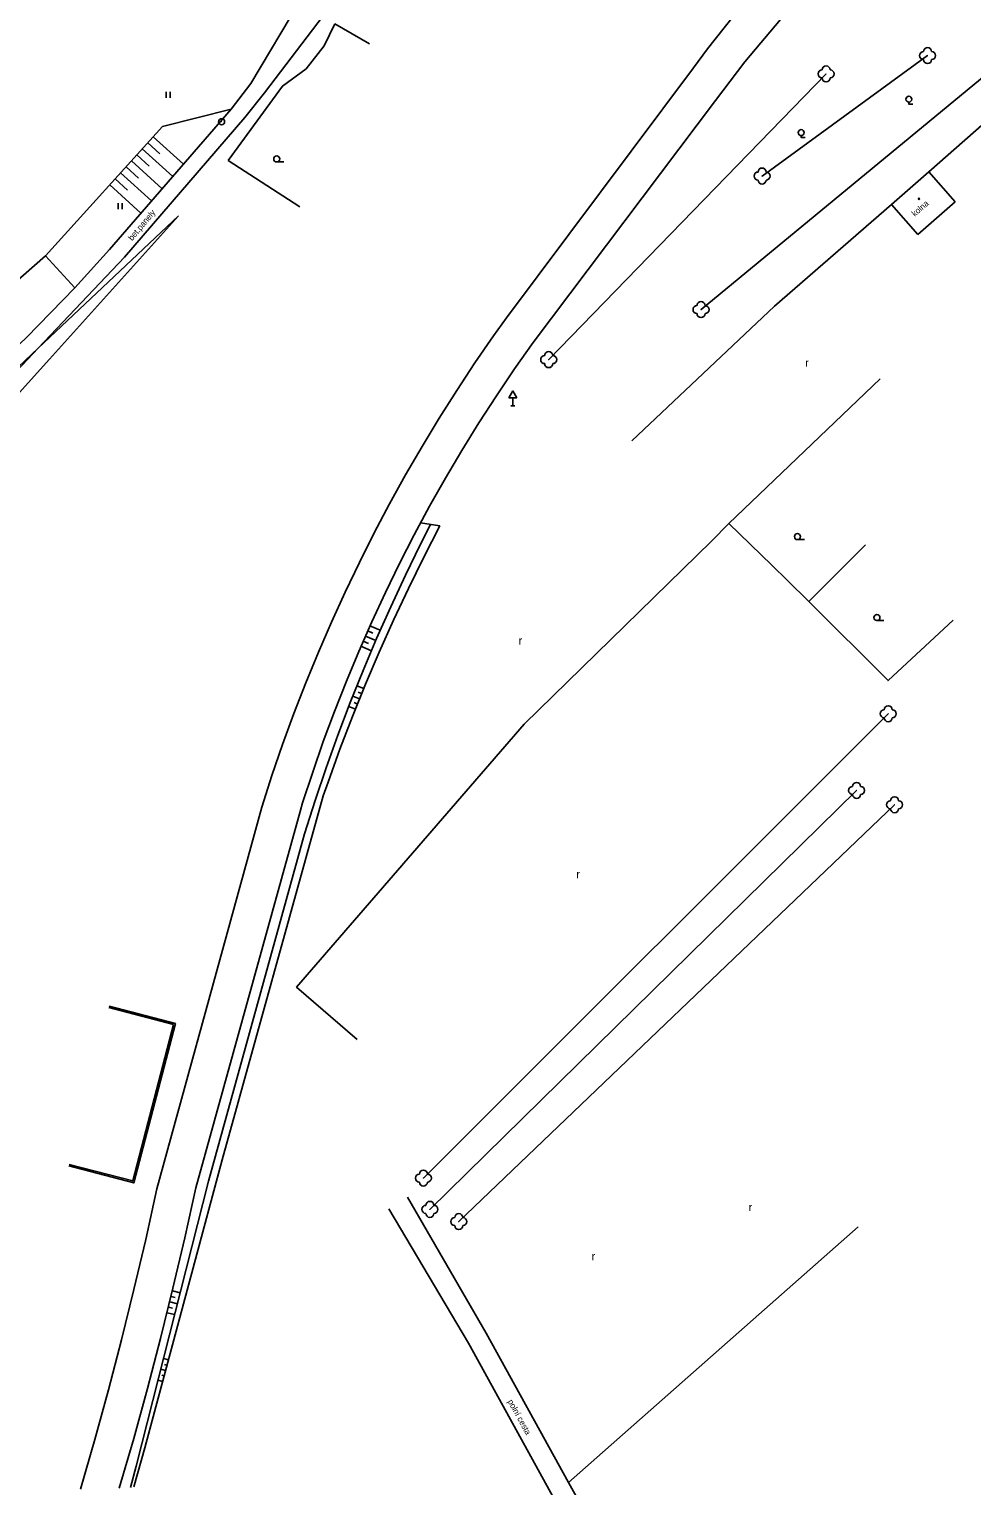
# Model space of a CAD drawing. Extents: x -544674 to -541478, y -1199076 to -1195527.
# Drawn here: x -543908.9 to -543791.2, y -1197598.9 to -1197417 of the extents above; entities that cross this region are included whole.
import ezdxf

# ---------------------------------------------------------------- set-up
doc = ezdxf.new("R2010")
doc.units = 0
for name, color, linetype in [('BUDOVY_MĚŘ', 7, 'Continuous'), ('BUDOVY_NEMĚŘ', 7, 'Continuous'), ('MAP_ZN_BP', 7, 'Continuous'), ('POMOC_POPIS', 7, 'Continuous'), ('ROZHRANÍ_PLOCH', 7, 'Continuous'), ('VÝŠKOPIS', 7, 'Continuous'), ('ZELEŇ', 7, 'Continuous'), ('ZN_BUDOV', 7, 'Continuous'), ('ZN_DOPLŇKOVÉ', 7, 'Continuous'), ('ZN_KULTUR', 7, 'Continuous')]:
    doc.layers.add(name, color=color, linetype=linetype)

msp = doc.modelspace()

# ---------------------------------------------------------------- linework, layer by layer
at = {"layer": 'BUDOVY_MĚŘ'}
for points in [[(-543870.77, -1197416.3), (-543866.43, -1197418.78)], [(-543801.25, -1197438.87), (-543796.59, -1197434.77)]]:
    msp.add_lwpolyline(points, dxfattribs=at)
at = {"layer": 'BUDOVY_NEMĚŘ'}
for points in [[(-543793.29, -1197438.52), (-543796.59, -1197434.77)], [(-543797.95, -1197442.62), (-543801.25, -1197438.87)], [(-543793.29, -1197438.52), (-543797.95, -1197442.62)]]:
    msp.add_lwpolyline(points, dxfattribs=at)
at = {"layer": 'MAP_ZN_BP'}
for radius in [0.375, 0.0005]:
    msp.add_circle((-543884.89, -1197428.531), radius, dxfattribs=at)
at = {"layer": 'ROZHRANÍ_PLOCH'}
for points in [[(-543807.01, -1197397.49), (-543812.18, -1197404.22), (-543824.2, -1197419.43), (-543825.96, -1197421.78)], [(-543799.94, -1197397.74), (-543819.57, -1197421.04), (-543823.21, -1197425.87)], [(-543872.33, -1197408.41), (-543875.02, -1197413.36), (-543881.23, -1197423.75), (-543883.69, -1197426.94)], [(-543869.19, -1197409.61), (-543872.22, -1197415.31), (-543879.55, -1197424.91), (-543882.01, -1197427.98)], [(-543825.96, -1197421.78), (-543849.33, -1197453.01), (-543850.94, -1197455.26), (-543853.27, -1197458.66), (-543855.53, -1197462.09), (-543857.73, -1197465.57), (-543859.86, -1197469.1), (-543861.93, -1197472.66), (-543863.92, -1197476.26), (-543865.84, -1197479.9), (-543867.69, -1197483.58), (-543869.47, -1197487.29), (-543871.18, -1197491.03), (-543872.81, -1197494.81), (-543874.37, -1197498.62), (-543875.86, -1197502.46), (-543877.27, -1197506.33), (-543878.6, -1197510.22), (-543879.86, -1197514.14), (-543892.97, -1197561.85), (-543894.36, -1197568.15), (-543895.83, -1197574.43), (-543897.38, -1197580.7), (-543899.01, -1197586.94), (-543900.71, -1197593.16), (-543902.49, -1197599.36)], [(-543823.21, -1197425.87), (-543846, -1197456.1), (-543848.32, -1197459.4), (-543850.57, -1197462.75), (-543852.76, -1197466.14), (-543854.88, -1197469.58), (-543856.93, -1197473.06), (-543858.92, -1197476.57), (-543860.83, -1197480.13), (-543862.67, -1197483.72), (-543864.44, -1197487.35), (-543866.14, -1197491.01), (-543867.76, -1197494.7), (-543869.31, -1197498.43), (-543870.79, -1197502.19), (-543872.19, -1197505.97), (-543873.52, -1197509.78), (-543874.77, -1197513.62), (-543875.1, -1197514.68), (-543888.1, -1197561.72), (-543889.48, -1197567.95), (-543890.96, -1197574.25), (-543892.52, -1197580.52), (-543894.15, -1197586.78), (-543895.87, -1197593.02), (-543897.66, -1197599.23)], [(-543925.38, -1197473.51), (-543907.78, -1197456.8), (-543897.03, -1197445.43), (-543882.01, -1197427.98)], [(-543883.69, -1197426.94), (-543898.88, -1197444.48), (-543903.21, -1197449.26), (-543909.24, -1197455.47), (-543925.14, -1197470.5)], [(-543861.68, -1197562.88), (-543851.84, -1197579.85), (-543841.58, -1197598.53), (-543835.5, -1197609.42), (-543829.31, -1197618.12), (-543823.7, -1197624.21), (-543819.24, -1197626.66), (-543813.49, -1197627.62), (-543807.65, -1197626.61)], [(-543863.99, -1197564.35), (-543854.05, -1197581.13), (-543837.84, -1197610.66), (-543831.7, -1197619.95), (-543825.41, -1197626.26), (-543819.82, -1197629.04), (-543813.7, -1197630.75), (-543809.54, -1197636.63)]]:
    msp.add_lwpolyline(points, dxfattribs=at)
at = {"layer": 'VÝŠKOPIS'}
for points in [[(-543883.69, -1197426.94), (-543892.25, -1197429.12), (-543906.87, -1197445.29), (-543933.32, -1197468.49)], [(-543890.98, -1197435.36), (-543894.79, -1197431.92)], [(-543892.59, -1197432.54), (-543894.11, -1197431.17)], [(-543889.66, -1197433.83), (-543893.43, -1197430.42)], [(-543892.31, -1197436.89), (-543896.14, -1197433.43)], [(-543893.94, -1197434.06), (-543895.46, -1197432.68)], [(-543896.62, -1197437.08), (-543898.18, -1197435.68)], [(-543893.63, -1197438.42), (-543897.5, -1197434.93)], [(-543895.28, -1197435.57), (-543896.82, -1197434.18)], [(-543894.96, -1197439.95), (-543898.86, -1197436.43)], [(-543890.27, -1197440.27), (-543907.78, -1197456.8), (-543924.56, -1197474.6)], [(-543922.99, -1197476.59), (-543906.4, -1197458.18), (-543890.27, -1197440.27)], [(-543866.65, -1197492.14), (-543865.99, -1197492.42)], [(-543866.37, -1197491.49), (-543865.08, -1197492.05)], [(-543867.21, -1197493.42), (-543866.56, -1197493.7)], [(-543866.93, -1197492.78), (-543865.64, -1197493.34)], [(-543867.49, -1197494.06), (-543866.19, -1197494.63)], [(-543867.15, -1197499.32), (-543867.99, -1197498.99)], [(-543867.67, -1197500.62), (-543868.51, -1197500.29)], [(-543867.93, -1197501.27), (-543868.35, -1197501.1)], [(-543867.41, -1197499.97), (-543867.82, -1197499.81)], [(-543868.19, -1197501.92), (-543869.02, -1197501.59)], [(-543891.37, -1197575.95), (-543890.4, -1197576.19)], [(-543891.2, -1197575.27), (-543890.7, -1197575.4)], [(-543891.04, -1197574.59), (-543890.06, -1197574.83)], [(-543891.71, -1197577.31), (-543890.75, -1197577.55)], [(-543891.54, -1197576.63), (-543891.02, -1197576.76)], [(-543891.53, -1197583.18), (-543892.13, -1197583.02)], [(-543891.9, -1197584.53), (-543892.48, -1197584.38)], [(-543891.71, -1197583.86), (-543892.01, -1197583.78)], [(-543892.26, -1197585.89), (-543892.82, -1197585.73)], [(-543892.08, -1197585.21), (-543892.37, -1197585.13)]]:
    msp.add_lwpolyline(points, dxfattribs=at)
at = {"layer": 'ZELEŇ'}
for points in [[(-543825.03, -1197451.99), (-543784.69, -1197418.73)], [(-543817.41, -1197435.31), (-543796.74, -1197420.27)], [(-543844.05, -1197458.25), (-543809.41, -1197422.55)], [(-543906.87, -1197445.29), (-543903.21, -1197449.26)], [(-543859.69, -1197560.5), (-543801.66, -1197502.48)], [(-543858.89, -1197564.4), (-543805.6, -1197512.07)], [(-543855.27, -1197565.93), (-543800.87, -1197513.85)], [(-543841.58, -1197598.53), (-543805.4, -1197566.57)]]:
    msp.add_lwpolyline(points, dxfattribs=at)
for centre in [(-543796.74, -1197420.27), (-543809.41, -1197422.55), (-543817.41, -1197435.31), (-543825.03, -1197451.99), (-543844.05, -1197458.25), (-543801.66, -1197502.48), (-543805.6, -1197512.07), (-543800.87, -1197513.85), (-543859.69, -1197560.5), (-543858.89, -1197564.4), (-543855.27, -1197565.93)]:
    msp.add_circle(centre, 0.0005, dxfattribs=at)
for centre, start, end in [((-543796.74, -1197419.77), 0, 179.99999), ((-543797.24, -1197420.27), 89.99999, 269.99999), ((-543796.74, -1197420.77), 179.99999, 359.99999), ((-543796.24, -1197420.27), 270, 89.99999), ((-543809.91, -1197422.55), 89.99999, 269.99999), ((-543809.41, -1197422.05), 0, 179.99999), ((-543809.41, -1197423.05), 179.99999, 359.99999), ((-543808.91, -1197422.55), 270, 89.99999), ((-543817.91, -1197435.31), 89.99999, 269.99999), ((-543817.41, -1197434.81), 0, 179.99999), ((-543817.41, -1197435.81), 179.99999, 359.99999), ((-543816.91, -1197435.31), 270, 89.99999), ((-543825.53, -1197451.99), 89.99999, 269.99999), ((-543825.03, -1197451.49), 0, 179.99999), ((-543824.53, -1197451.99), 270, 89.99999), ((-543825.03, -1197452.49), 179.99999, 359.99999), ((-543844.05, -1197457.75), 0, 179.99999), ((-543844.55, -1197458.25), 89.99999, 269.99999), ((-543844.05, -1197458.75), 179.99999, 359.99999), ((-543843.55, -1197458.25), 270, 89.99999), ((-543802.16, -1197502.48), 89.99999, 269.99999), ((-543801.66, -1197501.98), 0, 179.99999), ((-543801.66, -1197502.98), 179.99999, 359.99999), ((-543801.16, -1197502.48), 270, 89.99999), ((-543806.1, -1197512.07), 89.99999, 269.99999), ((-543805.6, -1197511.57), 0, 179.99999), ((-543805.1, -1197512.07), 270, 89.99999), ((-543805.6, -1197512.57), 179.99999, 359.99999), ((-543801.37, -1197513.85), 89.99999, 269.99999), ((-543800.87, -1197513.35), 0, 179.99999), ((-543800.37, -1197513.85), 270, 89.99999), ((-543800.87, -1197514.35), 179.99999, 359.99999), ((-543859.69, -1197560), 0, 179.99999), ((-543860.19, -1197560.5), 89.99999, 269.99999), ((-543859.69, -1197561), 179.99999, 359.99999), ((-543859.19, -1197560.5), 270, 89.99999), ((-543859.39, -1197564.4), 89.99999, 269.99999), ((-543858.89, -1197563.9), 0, 179.99999), ((-543858.89, -1197564.9), 179.99999, 359.99999), ((-543858.39, -1197564.4), 270, 89.99999), ((-543855.27, -1197565.43), 0, 179.99999), ((-543855.77, -1197565.93), 89.99999, 269.99999), ((-543855.27, -1197566.43), 179.99999, 359.99999), ((-543854.77, -1197565.93), 270, 89.99999)]:
    msp.add_arc(centre, 0.5, start, end, dxfattribs=at)
at = {"layer": 'ZN_BUDOV'}
msp.add_circle((-543797.8, -1197438.16), 0.0875, dxfattribs=at)
at = {"layer": 'ZN_DOPLŇKOVÉ'}
for p, q in [((-543848.51, -1197462.144), (-543849.01, -1197463.01)), ((-543849.01, -1197463.01), (-543848.01, -1197463.01)), ((-543848.51, -1197462.144), (-543848.01, -1197463.01)), ((-543848.51, -1197464.01), (-543848.51, -1197463.01)), ((-543848.76, -1197464.01), (-543848.26, -1197464.01))]:
    msp.add_line(p, q, dxfattribs=at)
for points in [[(-543884.07, -1197433.36), (-543877.29, -1197424.07), (-543874.32, -1197421.91), (-543872.09, -1197419.04), (-543870.77, -1197416.3)], [(-543782.05, -1197421.99), (-543796.59, -1197434.77)], [(-543884.07, -1197433.36), (-543875.12, -1197439.17)], [(-543801.25, -1197438.87), (-543815.86, -1197451.56), (-543833.66, -1197468.39)], [(-543802.65, -1197460.64), (-543821.56, -1197478.74)], [(-543896.28, -1197599.15), (-543895.55, -1197596.5), (-543886.53, -1197560.9), (-543874.52, -1197517.47), (-543873.21, -1197513.34), (-543871.82, -1197509.23), (-543870.36, -1197505.15), (-543868.83, -1197501.1), (-543867.21, -1197497.07), (-543865.53, -1197493.08), (-543863.77, -1197489.12), (-543861.94, -1197485.19), (-543860.04, -1197481.29), (-543858.79, -1197478.84)], [(-543860.04, -1197478.64), (-543857.65, -1197479.03), (-543859.65, -1197482.91), (-543861.57, -1197486.83), (-543863.43, -1197490.79), (-543865.21, -1197494.78), (-543866.92, -1197498.8), (-543868.56, -1197502.85), (-543870.12, -1197506.93), (-543871.6, -1197511.03), (-543872.2, -1197512.76), (-543884.84, -1197558.22), (-543894.49, -1197594.21), (-543895.85, -1197599.07)], [(-543821.56, -1197478.74), (-543823.72, -1197480.94)], [(-543821.56, -1197478.74), (-543816.2, -1197483.92)], [(-543823.72, -1197480.94), (-543847.13, -1197503.8), (-543875.53, -1197536.63), (-543867.97, -1197543.17)], [(-543804.48, -1197481.4), (-543811.55, -1197488.48)], [(-543816.2, -1197483.92), (-543814.23, -1197485.83)], [(-543814.23, -1197485.83), (-543811.55, -1197488.48)], [(-543811.55, -1197488.48), (-543801.67, -1197498.35), (-543793.53, -1197490.8)], [(-543903.97, -1197558.97), (-543895.85, -1197561.09), (-543890.65, -1197541.17), (-543898.92, -1197539.01)], [(-543890.89, -1197541.31), (-543898.97, -1197539.2)], [(-543903.91, -1197558.78), (-543895.99, -1197560.85), (-543890.89, -1197541.31)]]:
    msp.add_lwpolyline(points, dxfattribs=at)
at = {"layer": 'ZN_KULTUR'}
for p, q in [((-543891.8, -1197425.545), (-543891.8, -1197424.795)), ((-543891.3, -1197425.545), (-543891.3, -1197424.795)), ((-543878.01, -1197433.555), (-543877.135, -1197433.555)), ((-543897.79, -1197439.455), (-543897.79, -1197438.705)), ((-543897.29, -1197439.455), (-543897.29, -1197438.705)), ((-543812.99, -1197480.735), (-543812.115, -1197480.735)), ((-543803.06, -1197490.845), (-543802.185, -1197490.845))]:
    msp.add_line(p, q, dxfattribs=at)
for points in [[(-543799.08, -1197426.085), (-543799.08, -1197426.335), (-543798.58, -1197426.335)], [(-543812.52, -1197430.265), (-543812.52, -1197430.515), (-543812.02, -1197430.515)]]:
    msp.add_lwpolyline(points, dxfattribs=at)
for centre in [(-543799.08, -1197425.71), (-543812.52, -1197429.89), (-543878.01, -1197433.18), (-543812.99, -1197480.36), (-543803.06, -1197490.47)]:
    msp.add_circle(centre, 0.375, dxfattribs=at)

# ---------------------------------------------------------------- texts
at = {"layer": 'POMOC_POPIS'}
for s, rotation, p in [('kolna', 41.33999, (-543798.33, -1197440.42)), ('bet.panely', 50.17999, (-543896.06, -1197443.46)), ('polní cesta', 298.76002, (-543849.19, -1197588.4))]:
    msp.add_text(s, height=0.75, rotation=rotation, dxfattribs=at).set_placement(p)
at = {"layer": 'ZN_KULTUR'}
for p in [(-543812.018, -1197459.142), (-543847.798, -1197493.842), (-543840.588, -1197523.032), (-543819.078, -1197564.622), (-543838.698, -1197570.762)]:
    msp.add_text('r', height=1, dxfattribs=at).set_placement(p)

doc.saveas('drawing.dxf')
